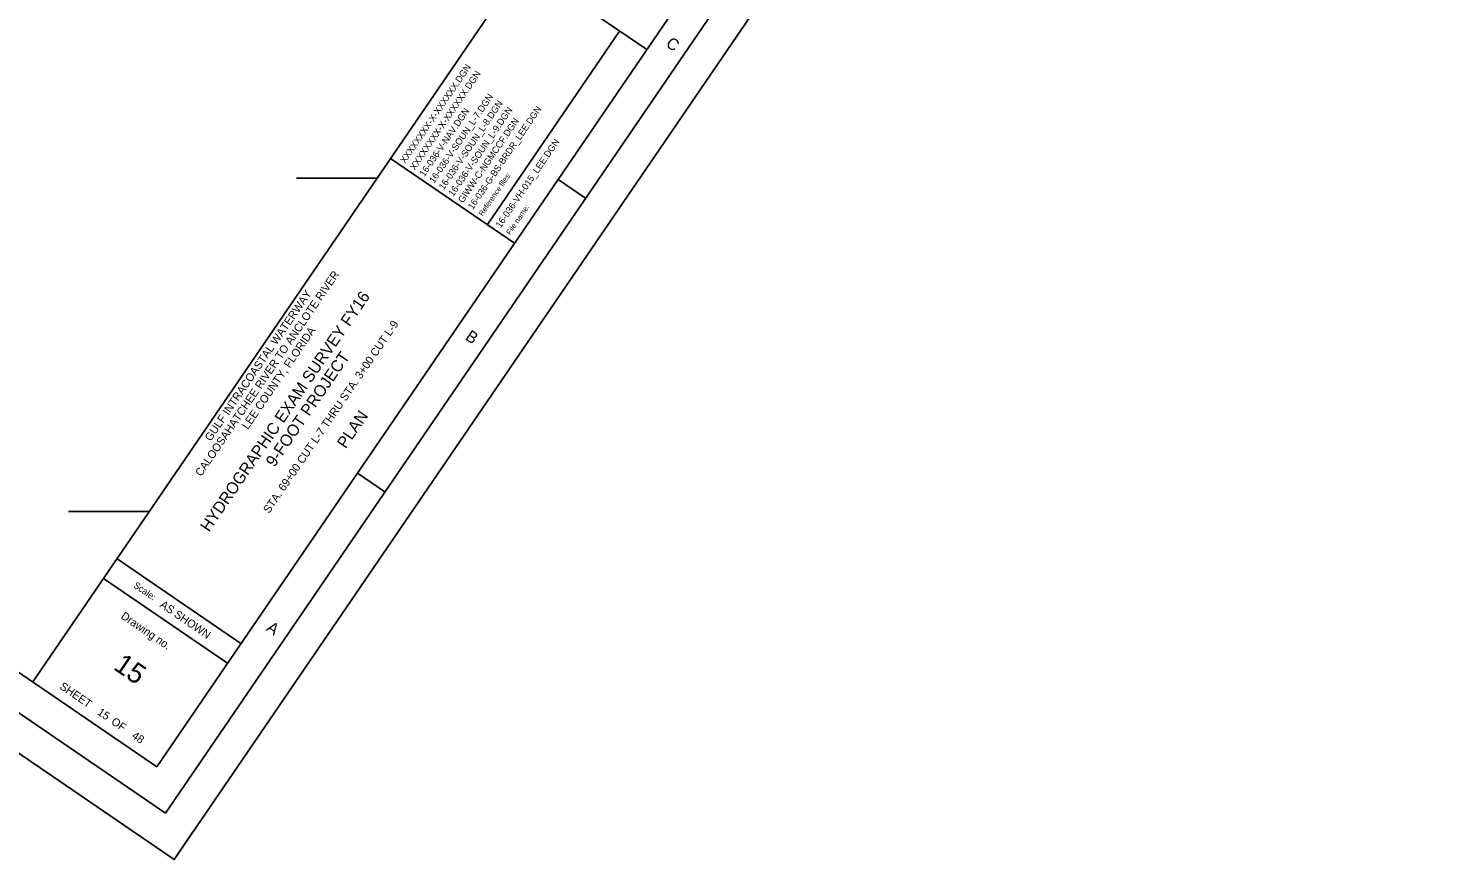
# Model space of a CAD drawing. Extents: x 605889 to 611440, y 782978 to 788269.
# Drawn here: x 609303 to 611440, y 782978 to 784224 of the extents above; entities that cross this region are included whole.
import ezdxf

# ---------------------------------------------------------------- set-up
doc = ezdxf.new("R2010")
doc.units = 0
for name, color, linetype in [('G-ANNO-NPLT', 7, 'Continuous'), ('G-ANNO-TEXT-DRWG', 7, 'Continuous'), ('G-ANNO-TEXT-PROJ', 7, 'Continuous'), ('G-ANNO-TEXT-TTLB', 7, 'Continuous'), ('G-ANNO-TTLB', 7, 'Continuous'), ('V-TOPO-COOR-STAT', 7, 'Continuous')]:
    doc.layers.add(name, color=color, linetype=linetype)

msp = doc.modelspace()

# ---------------------------------------------------------------- linework, layer by layer
at = {"layer": 'G-ANNO-NPLT'}
msp.add_lwpolyline([(607807.9, 788268.5), (611440.1, 785785.2), (609521.2, 782978.5), (605889, 785461.8)], close=True, dxfattribs=at)
msp.add_lwpolyline([(609549.5, 783019.7), (609521.3, 782978.4), (609480, 783006.7)], dxfattribs=at)
at = {"layer": 'G-ANNO-TTLB'}
for p, q in [((611115.4, 785886.1), (609309.3, 783244.5)), ((610043.3, 784320.1), (610230, 784192.4)), ((610189.3, 784220.2), (609991, 783930.2)), ((609845.9, 784029.3), (610031.7, 783902.4)), ((610138.3, 783969.7), (610097.1, 783998)), ((609837.3, 783529.5), (609796.1, 783557.7)), ((609435.6, 783429.2), (609621.4, 783302.2)), ((609415.5, 783399.8), (609601.2, 783272.7))]:
    msp.add_line(p, q, dxfattribs=at)
for points in [[(605958.5, 785474.9), (609508.1, 783048), (611370.6, 785772.2), (607821, 788199)], [(611301.1, 785759.1), (607895.9, 788087.2), (606089.9, 785445.6), (609495.1, 783117.5)]]:
    msp.add_lwpolyline(points, close=True, dxfattribs=at)
at = {"layer": 'V-TOPO-COOR-STAT'}
for p, q in [((609704.7, 784000), (609825.8, 784000)), ((609362.9, 783500), (609484, 783500))]:
    msp.add_line(p, q, dxfattribs=at)

# ---------------------------------------------------------------- texts
at = {"layer": 'G-ANNO-TEXT-DRWG'}
for s, height, rotation, p in [('XXXXXXXX-X-XXXXXX.DGN', 10, 55.6398, (609867.7, 784020.9)), ('XXXXXXXX-X-XXXXXX.DGN', 10, 55.6398, (609882.2, 784011)), ('16-036-V-SOUN_L-7.DGN', 10, 55.6398, (609911.1, 783991.3)), ('16-036-V-NAV.DGN', 10, 55.6398, (609896.6, 784001.2)), ('16-036-V-SOUN_L-8.DGN', 10, 55.6398, (609925.5, 783981.4)), ('16-036-V-SOUN_L-9.DGN', 10, 55.6398, (609940, 783971.5)), ('GIWW-C-NGMCCF.DGN', 10, 55.6398, (609954.4, 783961.7)), ('16-036-VH-015_LEE.DGN', 10, 55.6398, (610010.9, 783924.3)), ('STA. 69+00 CUT L-7 THRU STA. 3+00 CUT L-9', 12, 55.6398, (609663.7, 783496.3)), ('PLAN', 17.5, 55.6398, (609778.6, 783593.2)), ('15', 30, 325.6398, (609428.7, 783264.4)), (' 15          48', 12, 325.6398, (609401.3, 783199.2))]:
    msp.add_text(s, height=height, rotation=rotation, dxfattribs=at).set_placement(p)
at = {"layer": 'G-ANNO-TEXT-PROJ'}
for s, height, p in [('16-036-G-BS-BRDR_LEE.DGN', 9.8, (609969.2, 783952)), ('CALOOSAHATCHEE RIVER TO ANCLOTE RIVER', 12, (609561.8, 783551.7)), ('HYDROGRAPHIC EXAM SURVEY FY16', 17.5, (609573.5, 783468.3)), ('GULF INTRACOASTAL WATERWAY', 12, (609576.1, 783604.5)), ('LEE COUNTY, FLORIDA', 12, (609631.8, 783622.2)), ('9-FOOT PROJECT', 17.5, (609671.8, 783565.6))]:
    msp.add_text(s, height=height, rotation=55.6398, dxfattribs=at).set_placement(p)
at = {"layer": 'G-ANNO-TEXT-TTLB'}
for s, height, rotation, p in [('Reference files:', 8, 55.6398, (609983.9, 783942.1)), ('File name:', 8, 55.6398, (610025.3, 783914.1)), ('Scale:', 10, 325.6398, (609459.1, 783387.2)), ('Drawing no.', 12, 325.6398, (609440.3, 783340.7)), ('AS SHOWN', 12, 325.6398, (609498.8, 783357.8)), ('SHEET         OF', 12, 325.6398, (609348.4, 783235.3))]:
    msp.add_text(s, height=height, rotation=rotation, dxfattribs=at).set_placement(p)
at = {"layer": 'G-ANNO-TTLB'}
for s, p in [('C', (610257.4, 784198.3)), ('B', (609956.6, 783758.8)), ('A', (609658.2, 783322.4))]:
    msp.add_text(s, height=17.5, rotation=325.6398, dxfattribs=at).set_placement(p)

doc.saveas('drawing.dxf')
